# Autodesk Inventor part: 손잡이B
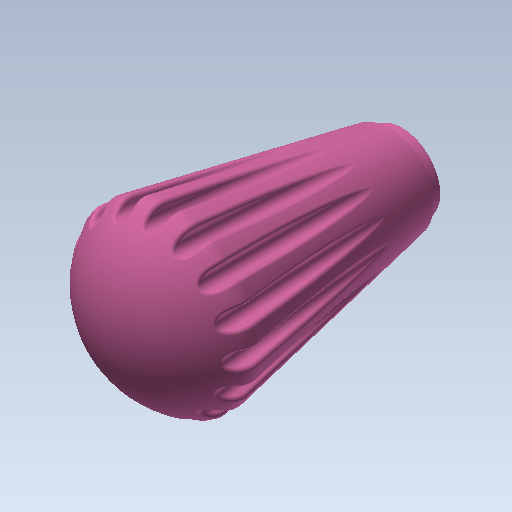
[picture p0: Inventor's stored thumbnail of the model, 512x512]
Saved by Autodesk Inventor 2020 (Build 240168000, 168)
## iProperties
Created: 2022-02
Part Number: 손잡이B
Material: ABS 플라스틱
Document SubType Name: Modeling
Designer: mdu-edu
Density: 1.06 g/cm^3
Mass: 11.2757 g
Surface Area: 35.9826 cm^2
Volume: 10.6375 cm^3
Appearance: 분홍색
Author: mdu-edu
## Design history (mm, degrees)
sketch "스케치1"
  geometry: L1 (0, 0)-(6.5, 0); L2 (6.5, 0)-(12.649, 32); L3 (0, 0)-(0, 40); A1 r 14 centre (0, 26) between (12.649, 32) and (0, 40)
  constraints: 6 end point, 2 point on circle, 1 centre point, 1 horizontal, 1 perpendicular, 1 point on line
  dimensions: "d4" = 40 distance from line of L1 L3.end; "d5" = 13 diameter of L1.end L3; "d6" = 32 distance from line of L1 L2.end; "d7" = 14 radius of A1
revolve "회전1" sketch "스케치1" stored, may be unused: angle "d8" = 90 deg
fillet "모깎기1" dims "d9" = 3
sketch "스케치2"
  geometry: C1 r 5.5 at (0, 0); 1 further point
  constraints: 1 centre point, 1 coincident
  dimensions: "d24" = 11 diameter of C1
extrude "돌출1" join sketch "스케치2" distance "d26" = 2; taper "d27" = 0 deg
hole "구멍1" diameter "d17" = 6.647; stored, may be unused: countersink angle "d21" = 90 deg, drill point angle "d23" = 118 deg; dims "d18" = 14, "d19" = 4, "d20" = 2, "d22" = 16, "d46" = 10, "d47" = 10
fillet "모깎기2" dims "d30" = 1
sketch "스케치3"
  geometry: L1 (12.451, 30.97)-(6.5, 0) reference; L2 (8.037, 8)-(10.806, 34.901); L3 (-5.5, -2)-(5.5, -2) reference; A1 r 14 centre (0, 26) between (12.097, 33.046) and (-12.097, 33.046) reference; A2 r 3 centre (9.505, 31.536) between (12.451, 30.97) and (12.097, 33.046) reference; 1 further point
  constraints: 2 end point, 1 point on circle, 1 point on line
  dimensions: "d31" = 5 deg angle of L1 L2; "d32" = 10 distance from line of L3 L2.start
extrude "돌출2" cut sketch "스케치3" stored distance "d33" = 2; taper "d34" = 0 deg
fillet "모깎기3" dims "d35" = 1
fillet "모깎기4" dims "d36" = 0.5
node "솔리드1"
pattern_circular "원형 패턴1" dims angle "d38" = 360 deg
